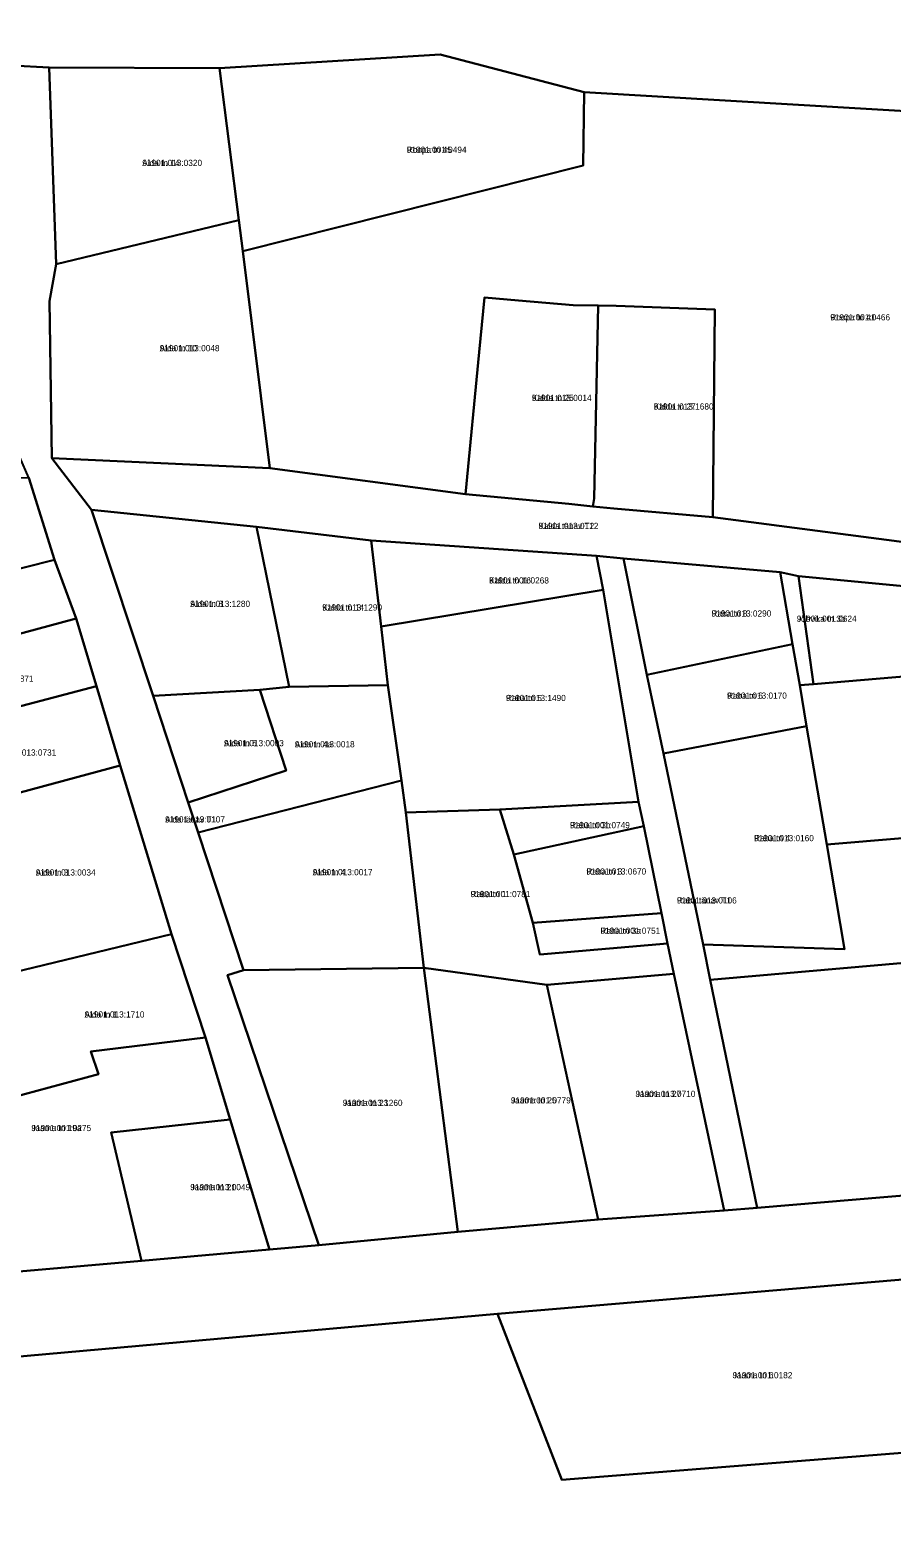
# Model space of a CAD drawing. Extents: x 675810 to 681273, y 6411190 to 6417565.
# Drawn here: x 679201.2 to 679410.2, y 6413542.7 to 6413908.4 of the extents above; entities that cross this region are included whole.
import ezdxf

# ---------------------------------------------------------------- set-up
doc = ezdxf.new("R2010")
doc.units = 0
for name, color, linetype in [('L_AADRESS', 7, 'Continuous'), ('PIIR', 7, 'Continuous'), ('TUNNUS', 7, 'Continuous')]:
    doc.layers.add(name, color=color, linetype=linetype)

msp = doc.modelspace()

# ---------------------------------------------------------------- linework, layer by layer
at = {"layer": 'PIIR'}
for points in [[(679421.76, 6413888.24), (679335.58, 6413893.31), (679300.66, 6413902.45), (679247.15, 6413899.15), (679205.84, 6413899.28), (679196.66, 6413899.8), (679130.16, 6413903.57), (679097.63, 6413905.42), (679080.9, 6413904.04), (679065.06, 6413902.73), (679037.52, 6413900.45), (679020.27, 6413899.08), (679003.23, 6413897.62), (678963.4, 6413894.33), (678964.34, 6413913.29)], [(679184.59, 6413606.09), (679228.23, 6413609.96), (679259.28, 6413612.63), (679271.23, 6413613.71), (679304.96, 6413616.97), (679338.97, 6413619.96), (679369.52, 6413622.13), (679377.56, 6413622.8), (679464.88, 6413630.09)], [(679420.47, 6413606.05), (679314.57, 6413597.1), (678982.22, 6413567.37)], [(678984.06, 6413538.75), (678982.22, 6413567.37), (679314.57, 6413597.1), (679330.12, 6413556.83), (679423.93, 6413564.22)]]:
    msp.add_lwpolyline(points, dxfattribs=at)
for points in [[(679252.78, 6413854.78), (679251.79, 6413862.26), (679247.15, 6413899.15), (679300.66, 6413902.45), (679335.58, 6413893.31), (679335.31, 6413875.53)], [(679196.66, 6413899.8), (679205.84, 6413899.28), (679207.5, 6413851.58), (679205.9, 6413842.68), (679206.48, 6413804.54), (679216.05, 6413792.01), (679231.04, 6413746.94), (679239.56, 6413721.03), (679241.97, 6413713.76), (679252.97, 6413680.43), (679249.07, 6413679.21), (679271.23, 6413613.71), (679259.28, 6413612.63), (679249.72, 6413644.17), (679243.75, 6413664.08), (679235.52, 6413689.16), (679223.07, 6413730.04), (679217.3, 6413749.31), (679212.4, 6413765.71), (679207.07, 6413779.92), (679200.86, 6413799.83), (679198.73, 6413804.8), (679198.65, 6413842.84), (679197.16, 6413885.36)], [(679207.5, 6413851.58), (679205.84, 6413899.28), (679247.15, 6413899.15), (679251.79, 6413862.26)], [(679335.31, 6413875.53), (679335.58, 6413893.31), (679421.76, 6413888.24), (679424.94, 6413782.65), (679366.8, 6413790.25), (679367.26, 6413840.63), (679343.31, 6413841.55), (679338.92, 6413841.61), (679332.87, 6413841.7), (679319.66, 6413842.82), (679311.36, 6413843.52), (679310.1, 6413830.3), (679306.82, 6413795.82), (679259.36, 6413802.14), (679252.78, 6413854.78)], [(679251.79, 6413862.26), (679252.78, 6413854.78), (679259.36, 6413802.14), (679206.48, 6413804.54), (679205.9, 6413842.68), (679207.5, 6413851.58)], [(679331.83, 6413793.49), (679306.82, 6413795.82), (679310.1, 6413830.3), (679311.36, 6413843.52), (679319.66, 6413842.82), (679332.87, 6413841.7), (679338.92, 6413841.61), (679338, 6413794.82), (679337.65, 6413792.89)], [(679342.79, 6413792.36), (679337.65, 6413792.89), (679338, 6413794.82), (679338.92, 6413841.61), (679343.31, 6413841.55), (679367.26, 6413840.63), (679366.8, 6413790.25)], [(679206.48, 6413804.54), (679259.36, 6413802.14), (679306.82, 6413795.82), (679331.83, 6413793.49), (679337.65, 6413792.89), (679342.79, 6413792.36), (679366.8, 6413790.25), (679424.94, 6413782.65), (679454.1, 6413779.99), (679447.88, 6413770.24), (679387.51, 6413775.97), (679383.08, 6413776.94), (679345.09, 6413780.26), (679338.56, 6413780.89), (679283.9, 6413784.6), (679256.12, 6413787.89), (679216.05, 6413792.01)], [(679139.17, 6413800.08), (679200.86, 6413799.83), (679207.07, 6413779.92), (679192.67, 6413776.28), (679189.1, 6413787.94), (679180.37, 6413787.89), (679144.1, 6413788.04)], [(679256.12, 6413787.89), (679264.04, 6413749.08), (679256.87, 6413748.41), (679231.04, 6413746.94), (679216.05, 6413792.01)], [(679283.9, 6413784.6), (679286.31, 6413763.75), (679287.96, 6413749.56), (679264.04, 6413749.08), (679256.12, 6413787.89)], [(679283.9, 6413784.6), (679338.56, 6413780.89), (679340.21, 6413772.68), (679286.31, 6413763.75)], [(679152.9, 6413765.99), (679186.28, 6413774.66), (679192.67, 6413776.28), (679207.07, 6413779.92), (679212.4, 6413765.71), (679157.89, 6413750.98)], [(679340.21, 6413772.68), (679338.56, 6413780.89), (679345.09, 6413780.26), (679350.79, 6413752.06), (679354.81, 6413732.97), (679364.41, 6413686.6), (679366.15, 6413678.04), (679377.56, 6413622.8), (679369.52, 6413622.13), (679357.29, 6413679.5), (679355.78, 6413686.84), (679354.3, 6413694.21), (679350.01, 6413715.31), (679348.74, 6413721.21)], [(679345.09, 6413780.26), (679383.08, 6413776.94), (679386.12, 6413759.5), (679350.79, 6413752.06)], [(679391.21, 6413749.78), (679387.89, 6413749.54), (679386.12, 6413759.5), (679383.08, 6413776.94), (679387.51, 6413775.97)], [(679387.51, 6413775.97), (679447.88, 6413770.24), (679452.97, 6413755.04), (679391.21, 6413749.78)], [(679286.31, 6413763.75), (679340.21, 6413772.68), (679348.74, 6413721.21), (679315.11, 6413719.36), (679292.35, 6413718.66), (679291.24, 6413726.42), (679287.96, 6413749.56)], [(679212.4, 6413765.71), (679217.3, 6413749.31), (679162.87, 6413735.01), (679157.89, 6413750.98)], [(679350.79, 6413752.06), (679386.12, 6413759.5), (679387.89, 6413749.54), (679389.51, 6413739.6), (679354.81, 6413732.97)], [(679387.89, 6413749.54), (679391.21, 6413749.78), (679452.97, 6413755.04), (679468.03, 6413710.94), (679448.52, 6413715.46), (679449.39, 6413703.37), (679443.46, 6413702.85), (679431.54, 6413702.16), (679430.14, 6413713.89), (679394.41, 6413710.85), (679389.51, 6413739.6)], [(679162.87, 6413735.01), (679217.3, 6413749.31), (679223.07, 6413730.04), (679169.39, 6413715.58)], [(679239.56, 6413721.03), (679231.04, 6413746.94), (679256.87, 6413748.41), (679263.31, 6413728.84)], [(679256.87, 6413748.41), (679264.04, 6413749.08), (679287.96, 6413749.56), (679291.24, 6413726.42), (679241.97, 6413713.76), (679239.56, 6413721.03), (679263.31, 6413728.84)], [(679389.51, 6413739.6), (679394.41, 6413710.85), (679398.73, 6413685.48), (679364.41, 6413686.6), (679354.81, 6413732.97)], [(679223.07, 6413730.04), (679235.52, 6413689.16), (679183.96, 6413676.67), (679169.39, 6413715.58)], [(679291.24, 6413726.42), (679292.35, 6413718.66), (679296.66, 6413680.94), (679252.97, 6413680.43), (679241.97, 6413713.76)], [(679318.47, 6413708.44), (679315.11, 6413719.36), (679348.74, 6413721.21), (679350.01, 6413715.31)], [(679296.66, 6413680.94), (679292.35, 6413718.66), (679315.11, 6413719.36), (679318.47, 6413708.44), (679323.12, 6413691.89), (679324.85, 6413684.24), (679355.78, 6413686.84), (679357.29, 6413679.5), (679326.54, 6413676.89)], [(679354.3, 6413694.21), (679323.12, 6413691.89), (679318.47, 6413708.44), (679350.01, 6413715.31)], [(679394.41, 6413710.85), (679430.14, 6413713.89), (679431.54, 6413702.16), (679443.46, 6413702.85), (679444.69, 6413684.96), (679366.15, 6413678.04), (679364.41, 6413686.6), (679398.73, 6413685.48)], [(679323.12, 6413691.89), (679354.3, 6413694.21), (679355.78, 6413686.84), (679324.85, 6413684.24)], [(679215.96, 6413660.7), (679217.77, 6413655.18), (679193.81, 6413648.7), (679183.96, 6413676.67), (679235.52, 6413689.16), (679243.75, 6413664.08)], [(679453.9, 6413657.74), (679454.55, 6413651.77), (679460.82, 6413652.39), (679463.61, 6413641.23), (679464.88, 6413630.09), (679377.56, 6413622.8), (679366.15, 6413678.04), (679444.69, 6413684.96)], [(679249.07, 6413679.21), (679252.97, 6413680.43), (679296.66, 6413680.94), (679304.96, 6413616.97), (679271.23, 6413613.71)], [(679296.66, 6413680.94), (679326.54, 6413676.89), (679338.97, 6413619.96), (679304.96, 6413616.97)], [(679357.29, 6413679.5), (679369.52, 6413622.13), (679338.97, 6413619.96), (679326.54, 6413676.89)], [(679193.81, 6413648.7), (679217.77, 6413655.18), (679215.96, 6413660.7), (679243.75, 6413664.08), (679249.72, 6413644.17), (679220.83, 6413641.03), (679228.23, 6413609.96), (679184.59, 6413606.09), (679180.54, 6413636.74), (679177.8, 6413644.75), (679175.98, 6413650.08), (679162.66, 6413669.25), (679183.96, 6413676.67)], [(679220.83, 6413641.03), (679249.72, 6413644.17), (679259.28, 6413612.63), (679228.23, 6413609.96)], [(679330.12, 6413556.83), (679314.57, 6413597.1), (679420.47, 6413606.05), (679423.93, 6413564.22)]]:
    msp.add_lwpolyline(points, close=True, dxfattribs=at)

# ---------------------------------------------------------------- texts
at = {"layer": 'L_AADRESS'}
for s, p in [('Roopa tn 45', (679292.54, 6413878.62)), ('Aida tn 14', (679228.4, 6413875.43)), ('Roopa tn 41', (679395.25, 6413837.98)), ('Aida tn 10', (679232.63, 6413830.5)), ('Kalda tn 25', (679322.87, 6413818.44)), ('Kalda tn 27', (679352.45, 6413816.35)), ('Kalda tänav T2', (679324.51, 6413787.39)), ('Kalda tn 16', (679312.51, 6413774.18)), ('Aida tn 8', (679240.04, 6413768.5)), ('Kalda tn 14', (679272.04, 6413767.62)), ('Raba tn 8', (679366.45, 6413766.16)), ('Jõhvika tn 3b', (679387.14, 6413764.89)), ('Raba tn 5', (679316.6, 6413745.67)), ('Raba tn 6', (679370.22, 6413746.24)), ('Aida tn 6', (679248.22, 6413734.72)), ('Aida tn 4a', (679265.4, 6413734.44)), ('Aida tänav T1', (679233.94, 6413716.22)), ('Raba tn 3b', (679332.14, 6413714.83)), ('Raba tn 4', (679376.77, 6413711.68)), ('Aida tn 3', (679202.58, 6413703.36)), ('Aida tn 4', (679269.74, 6413703.43)), ('Raba tn 3', (679336.11, 6413703.6)), ('Raba tn 1', (679308.03, 6413698.12)), ('Raba tänav T1', (679358.06, 6413696.58)), ('Raba tn 3a', (679339.51, 6413689.23)), ('Aida tn 1', (679214.42, 6413668.93)), ('Jaama tn 23', (679277.02, 6413647.49)), ('Jaama tn 25', (679317.81, 6413648.09)), ('Jaama tn 27', (679348.03, 6413649.66)), ('Jaama tn 19a', (679201.5, 6413641.38)), ('Jaama tn 21', (679240.05, 6413627.05)), ('Jaama tn 6', (679371.56, 6413581.44))]:
    msp.add_text(s, height=1.5, dxfattribs=at).set_placement(p)
at = {"layer": 'TUNNUS'}
for s, p in [('91901:001:0494', (679292.54, 6413878.62)), ('91901:013:0320', (679228.4, 6413875.43)), ('91901:001:0466', (679395.25, 6413837.98)), ('91901:013:0048', (679232.63, 6413830.5)), ('91901:013:0014', (679322.87, 6413818.44)), ('91901:013:1680', (679352.45, 6413816.35)), ('91901:013:0112', (679324.51, 6413787.39)), ('91901:001:0268', (679312.51, 6413774.18)), ('91901:013:1280', (679240.04, 6413768.5)), ('91901:013:1290', (679272.04, 6413767.62)), ('91901:013:0290', (679366.45, 6413766.16)), ('91901:001:0624', (679387.14, 6413764.89)), ('91901:013:1871', (679187.53, 6413750.36)), ('91901:013:1490', (679316.6, 6413745.67)), ('91901:013:0170', (679370.22, 6413746.24)), ('91901:013:0003', (679248.22, 6413734.72)), ('91901:013:0018', (679265.4, 6413734.44)), ('91901:013:0731', (679193.04, 6413732.44)), ('91901:013:0107', (679233.94, 6413716.22)), ('91901:001:0749', (679332.14, 6413714.83)), ('91901:013:0160', (679376.77, 6413711.68)), ('91901:013:0034', (679202.58, 6413703.36)), ('91901:013:0017', (679269.74, 6413703.43)), ('91901:013:0670', (679336.11, 6413703.6)), ('91901:001:0781', (679308.03, 6413698.12)), ('91901:013:0106', (679358.06, 6413696.58)), ('91901:001:0751', (679339.51, 6413689.23)), ('91901:013:1710', (679214.42, 6413668.93)), ('91901:013:1260', (679277.02, 6413647.49)), ('91901:001:0779', (679317.81, 6413648.09)), ('91901:013:0710', (679348.03, 6413649.66)), ('91901:001:0275', (679201.5, 6413641.38)), ('91901:013:0049', (679240.05, 6413627.05)), ('91901:001:0182', (679371.56, 6413581.44))]:
    msp.add_text(s, height=1.5, dxfattribs=at).set_placement(p)

doc.saveas('drawing.dxf')
